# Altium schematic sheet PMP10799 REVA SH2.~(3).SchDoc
size 431 x 279 mm; Date: Not shown in title block; ApprovedBy: Not shown in title block; CheckedBy: Not shown in title block; Author: Not shown in title block; CompanyName: Not shown in title block; Engineer: Not shown in title block; Organization: Not shown in title block; Address1: Not shown in title block; Address2: Not shown in title block; Address3: Not shown in title block; Address4: Not shown in title block; DocumentNumber: 2; Revision: Use project parameter SCH_Rev; SheetNumber: 2; SheetTotal: 2; PageSetup: Record=PageOptions¦CenterHorizontal=True¦CenterVertical=True¦PrintScale=1.00¦XCorrection=1.00¦YCorrection=1.00¦PrintKind=0¦BorderSize=5000000¦LeftOffset=0¦BottomOffset=0¦Orientation=2¦PaperLength=1000¦PaperWidth=1000¦Scale=100¦PaperSource=15¦PrintQuality=600¦MediaType=1¦DitherType=10¦PaperKind=Letter¦PrintScaleMode=1
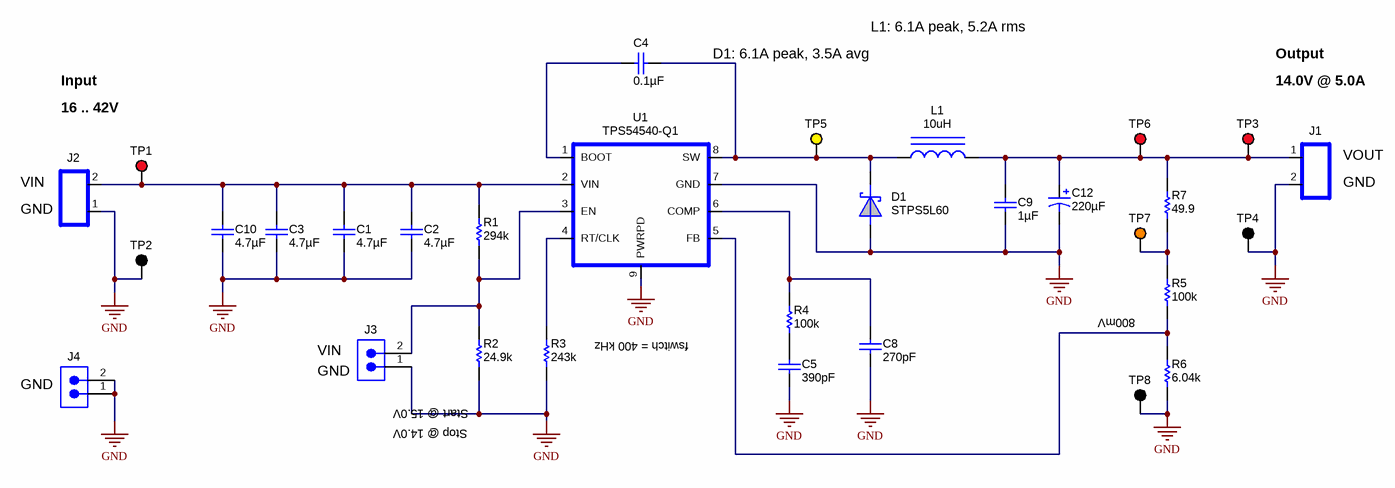
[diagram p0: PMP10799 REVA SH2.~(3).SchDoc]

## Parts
C1  ValueDisplayed: 4.7µF  [1210]  (hidden comment: GRM32ER71H475KA88L)
C2  ValueDisplayed: 4.7µF  [1210]  (hidden comment: GRM32ER71H475KA88L)
C3  ValueDisplayed: 4.7µF  [1210]  (hidden comment: GRM32ER71H475KA88L)
C4  ValueDisplayed: 0.1µF  [0603]  (hidden comment: C0603C104K8RACTU)
C5  ValueDisplayed: 390pF  [0603]  (hidden comment: GRM188R71H391KA01D)
C8  ValueDisplayed: 270pF  [0603]  (hidden comment: GRM188R71H271KA01D)
C9  ValueDisplayed: 1µF  [1206]  (hidden comment: GRM31MR71H105KA88L)
C10  ValueDisplayed: 4.7µF  [1210]  (hidden comment: GRM32ER71H475KA88L)
C12  ValueDisplayed: 220µF  [SM_RADIAL_F]  (hidden comment: EEE-FK1E221P)
D1  PartNumber: STPS5L60  [DO-201AD]  (hidden comment: STPS5L60SY)
J1  TBLK_15A_2X5.1MM  [TB_2X5.1MM]  (value not drawn)
J2  TBLK_15A_2X5.1MM  [TB_2X5.1MM]  (value not drawn)
J3  TSW-102-07-G-S  [TSW-102-07-G-S]  (value not drawn)
J4  TSW-102-07-G-S  [TSW-102-07-G-S]  (value not drawn)
L1  10uH  [SRP1250]
R1  value 294k  [0603]  (hidden comment: CRCW0603294KFKEA)
R2  value 24.9k  [0603]  (hidden comment: CRCW060324K9FKEA)
R3  value 243k  [0603]  (hidden comment: CRCW0603243KFKEA)
R4  value 100k  [0603]  (hidden comment: CRCW0603100KFKEA)
R5  value 100k  [0603]  (hidden comment: CRCW0603100KFKEA)
R6  value 6.04k  [0603]  (hidden comment: CRCW06036K04FKEA)
R7  value 49.9  [0603]  (hidden comment: CRCW060349R9FKEA)
TP1  5010  [Keystone5010]  (value not drawn)
TP2  5011  [Keystone5011]  (value not drawn)
TP3  5010  [Keystone5010]  (value not drawn)
TP4  5011  [Keystone5011]  (value not drawn)
TP5  5014  [Keystone5014]  (value not drawn)
TP6  5010  [Keystone5010]  (value not drawn)
TP7  5013  [Keystone5013]  (value not drawn)
TP8  5011  [Keystone5011]  (value not drawn)
U1  TPS54540-Q1  [DDA-8]

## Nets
GND: C1.2 C2.2 C3.2 C5.2 C8.2 C9.2 C10.2 C12.2(-) D1.2 J1.2 J2.1 J3.1 J4.1 J4.2 R2.1 R3.1 R6.1 TP2.1 TP4.1 TP8.1 U1.7(GND) U1.9(PWRPD)
NetC1_1: C1.1 C2.1 C3.1 C10.1 J2.2 R1.2 TP1.1 U1.2(VIN)
NetC4_1: C4.1 D1.1 L1.1 TP5.1 U1.8(SW)
NetC4_2: C4.2 U1.1(BOOT)
NetC5_1: C5.1 R4.1
NetC8_1: C8.1 R4.2 U1.6(COMP)
NetC9_1: C9.1 C12.1(+) J1.1 L1.2 R7.2 TP3.1 TP6.1
NetJ3_2: J3.2 R1.1 R2.2 U1.3(EN)
NetR3_2: R3.2 U1.4(RT/CLK)
NetR5_1: R5.1 R6.2 U1.5(FB)
NetR5_2: R5.2 R7.1 TP7.1

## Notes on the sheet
- L1: 6.1A peak, 5.2A rms
- D1: 6.1A peak, 3.5A avg
- Output
- Input
- 16 .. 42V
- 14.0V @ 5.0A
- (near J2) VIN
- (near J1) VOUT
- (near J1) GND
- (near J2) GND
- 800mV
- (near J4) GND
- (near J3) VIN
- (near J3) GND
- (near R3) fswitch = 400 kHz
- (near J3) Start @ 15.0V
- Stop @ 14.0V

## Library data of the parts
C1-C3 C10 = GRM32ER71H475KA88L: CAP, CERM, 4.7uF, 50V, +/-10%, X7R, 1210; Manufacturer: MuRata; Polarized: N; CompType: Capacitor; U/M: EA; Cap_F: 0.0000047; Tolerance_%: 10; ESR_Ohm: 0.002; Value1: 0.002 ohm; VDC_V: 50; TaMin_C: -55; TaMax_C: 125
C4 = C0603C104K8RACTU: CAP, CERM, 0.1uF, 10V, +/-10%, X7R, 0603; Manufacturer: Kemet; Polarized: N; CompType: Capacitor; U/M: EA; Cap_F: 0.0000001; Tolerance_%: 10; TaMin_C: -55; TaMax_C: 125
C5 = GRM188R71H391KA01D: CAP, CERM, 390pF, 50V, +/-10%, X7R, 0603; Manufacturer: MuRata; Polarized: N; CompType: Capacitor; U/M: EA; Cap_F: 0.00000000039; Tolerance_%: 10; Value1: Unknown; VDC_V: 50; TaMin_C: -55; TaMax_C: 125
C8 = GRM188R71H271KA01D: CAP, CERM, 270pF, 50V, +/-10%, X7R, 0603; Manufacturer: MuRata; Polarized: N; CompType: Capacitor; U/M: EA; Cap_F: 0.00000000027; Tolerance_%: 10; Value1: Unknown; VDC_V: 50; TaMin_C: -55; TaMax_C: 125
C9 = GRM31MR71H105KA88L: CAP, CERM, 1uF, 50V, +/-10%, X7R, 1206; Manufacturer: MuRata; Polarized: N; CompType: Capacitor; U/M: EA; Cap_F: 0.000001; Tolerance_%: 10; Value1: Unknown; VDC_V: 50; TaMin_C: -55; TaMax_C: 125
C12 = EEE-FK1E221P: CAP, AL, 220uF, 25V, +/-20%, 0.16 ohm, SMD; Manufacturer: Panasonic; Polarized: Y; CompType: Capacitor; U/M: EA; Cap_F: 0.00022; Tolerance_%: 20; VDC_V: 25; ESR_Ohm: 0.16; IRMS_A: 0.6; TaMin_C: -55; TaMax_C: 105; Cap_Case: F
D1 = D_SCHOT_STPS5L60: Diode, Schottky, 5A, 60V; Manufacturer: ST; Area: 126 mm
J1 J2 = TBLK_15A_2X5.1MM: Terminal Block, 2-pin, 15-A, 5.1mm; Manufacturer: OST; PartNumber: ED120/2DS; Alternate Manufacturer: Any; Alternate PartNumber: Equivalent; area: 141600; Value: ED120/2DS
J3 J4 = TSW-102-07-G-S: Header, TH, 100mil, 2x1, Gold plated, 230 mil above insulator; Manufacturer: Samtec, Inc.; U/M: EA
L1 = SRP1250-100M: Inductor, Powdered Iron, 10uH, 10A, 17mOhm; PartNumber: SRP1270-100M; Manufacturer: Bourns; Ind_H: 10.0E-6; ValueDisplayed: 10µH; Imax_A: 16; Irms: 10A @ 40C rise; Isat: 16A @ 20% inductance drop; DCR_ohm: 0.017; Value1: 0.017 ohm; U/M: EA
R1 = CRCW0603294KFKEA: RES, 294k ohm, 1%, 0.1W, 0603; Manufacturer: Vishay-Dale; CompType: Resistor; Res_ohm: 294000; Tolerance_%: 1; Power_W: 0.1; VDC_V: 75; TempCo: 100 ppm/C; EIA_Code: E96; U/M: EA
R2 = CRCW060324K9FKEA: RES, 24.9k ohm, 1%, 0.1W, 0603; Manufacturer: Vishay-Dale; CompType: Resistor; Res_ohm: 24900; Value_Code: 24k9; Tolerance_%: 1; Power_W: 0.1; VDC_V: 75; TempCo: 100 ppm/C; EIA_Code: E96; U/M: EA
R3 = CRCW0603243KFKEA: RES, 243k ohm, 1%, 0.1W, 0603; Manufacturer: Vishay-Dale; Alternate Manufacturer: Any; Alternate PartNumber: Equivalent; CompType: Resistor; Res_ohm: 243000; Tolerance_%: 1; Power_W: 0.1; VDC_V: 75; TempCo: 100 ppm/C; EIA_Code: E96; U/M: EA
R4 R5 = CRCW0603100KFKEA: RES, 100k ohm, 1%, 0.1W, 0603; Manufacturer: Vishay-Dale; CompType: Resistor; Res_ohm: 100000; Tolerance_%: 1; Power_W: 0.1; VDC_V: 75; TempCo: 100 ppm/C; EIA_Code: E96; U/M: EA
R6 = CRCW06036K04FKEA: RES, 6.04k ohm, 1%, 0.1W, 0603; Manufacturer: Vishay-Dale; CompType: Resistor; Res_ohm: 6040; Value_Code: 6k04; Tolerance_%: 1; Power_W: 0.1; VDC_V: 75; TempCo: 100 ppm/C; EIA_Code: E96; U/M: EA
R7 = CRCW060349R9FKEA: RES, 49.9 ohm, 1%, 0.1W, 0603; Manufacturer: Vishay-Dale; Alternate Manufacturer: Any; Alternate PartNumber: Equivalent; CompType: Resistor; Value_Code: 49R9; Tolerance_%: 1; Power_W: 0.1; VDC_V: 75; TempCo: 100 ppm/C; EIA_Code: E96; U/M: EA
TP1 TP3 TP6 = 5010: Test Point, TH, Multipurpose, Red; Manufacturer: Keystone; CompType: Test Point Loop; U/M: EA
TP2 TP4 TP8 = 5011: Test Point, TH, Multipurpose, Black; Manufacturer: Keystone; CompType: Test Point Loop; U/M: EA
TP5 = 5014: Test Point, TH Multipurpose, Yellow; Manufacturer: Keystone; CompType: Test Point Loop; U/M: EA
TP7 = 5013: Test Point, TH, Multipurpose, Orange; Manufacturer: Keystone; CompType: Test Point Loop; U/M: EA
U1 = TPS54360DDA: IC, 42V, 5A, Low Iq, Current Mode, Non-Synchronous Monolithic Buck; Manufacturer: TI; PartNumber: TPS54540DDA; Alternate Manufacturer: None; Alternate PartNumber: Equivalent; Area: 48.94 mm; Value: TPS54540DDA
